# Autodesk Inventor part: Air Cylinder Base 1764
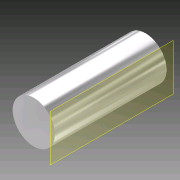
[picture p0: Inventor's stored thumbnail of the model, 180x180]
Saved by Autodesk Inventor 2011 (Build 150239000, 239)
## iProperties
Created: 2010-01
Part Number: Air Cylinder Base 1764
Document SubType Name: Modeling
Designer: cmcfadden
Density: 1 g/cm^3
Author: cmcfadden
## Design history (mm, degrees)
sketch "Sketch1"
  geometry: C1 r 26.416 at (10.426, -13.014); 1 further point
  constraints: 1 centre point
  dimensions: "d0" = 52.832 diameter of C1
extrude "Extrusion1" new body sketch "Sketch1" distance "d1" = 139.7508; taper "d2" = 0 deg
workplane "Work Plane1"
sketch "Sketch2"
  geometry: 1 further point
body "Solid1"
other parameters: "d3" = 38.1
